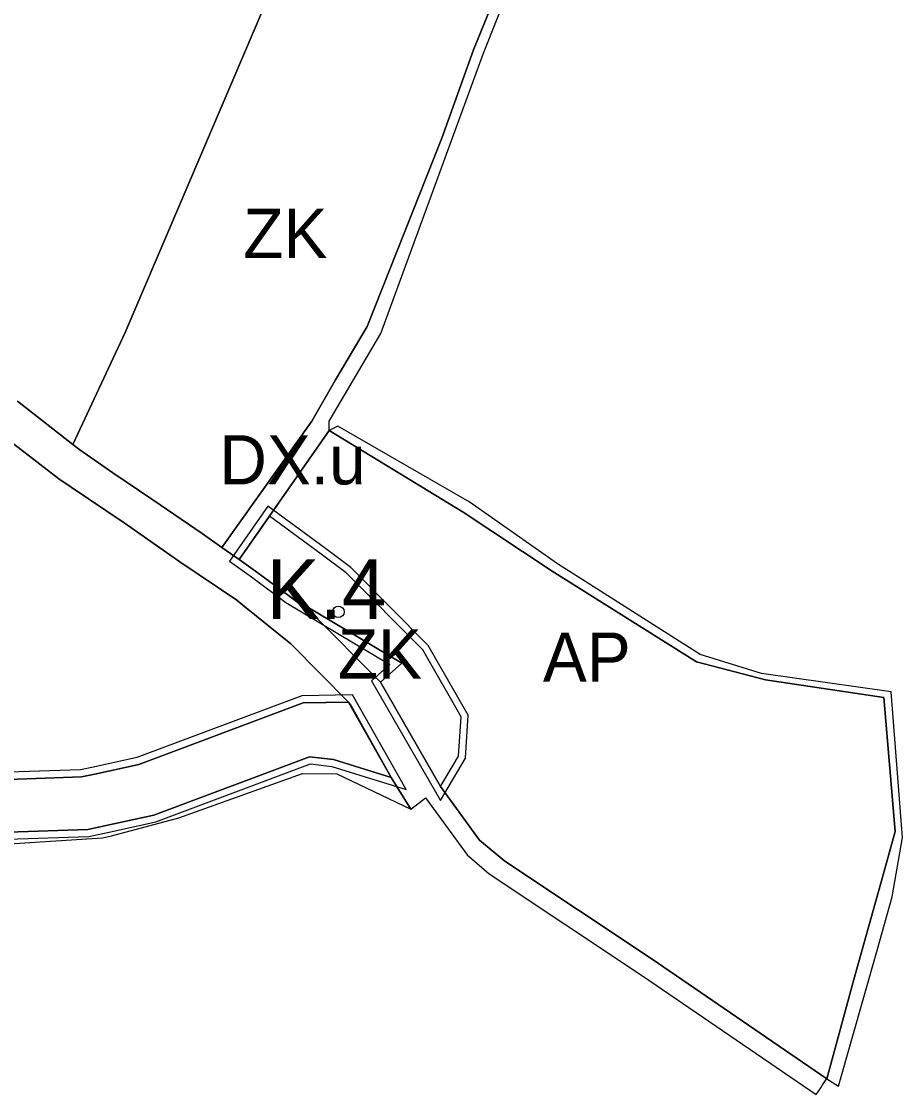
# Model space of a CAD drawing. Extents: x -555509 to -553005, y -1186756 to -1182560.
# Drawn here: x -553255.9 to -553005.3, y -1186113.4 to -1185808.2 of the extents above; entities that cross this region are included whole.
import ezdxf

# ---------------------------------------------------------------- set-up
doc = ezdxf.new("R2010")
doc.units = 0
for name, color, linetype in [('Level 26', 7, 'Continuous'), ('Level 46', 7, 'Continuous'), ('Level 56', 7, 'Continuous'), ('Level 59', 7, 'Continuous'), ('Level 63', 7, 'Continuous'), ('navrh_ZK', 7, 'Continuous'), ('OBRYS_PLOCH', 7, 'Continuous'), ('stav_AP', 7, 'Continuous'), ('stav_DS', 7, 'Continuous'), ('stav_ZK', 7, 'Continuous')]:
    doc.layers.add(name, color=color, linetype=linetype)

msp = doc.modelspace()

# ---------------------------------------------------------------- linework, layer by layer
at = {"layer": 'Level 26'}
for p, q in [((-553115.78, -1185787.77), (-553127.36, -1185816.34)), ((-553127.36, -1185816.34), (-553136.4, -1185841.45)), ((-553153.76, -1185896.92), (-553124.49, -1185817.28)), ((-553136.4, -1185841.45), (-553157.6, -1185894.95)), ((-553157.6, -1185894.95), (-553166.61, -1185910.14)), ((-553168.42, -1185921.93), (-553153.76, -1185896.92)), ((-553166.61, -1185910.14), (-553173.3, -1185921.88)), ((-553173.3, -1185921.88), (-553198.95, -1185957.78)), ((-553168.4, -1185924.59), (-553168.42, -1185921.93)), ((-553165.97, -1185923.29), (-553168.4, -1185924.59)), ((-553128.55, -1185944.85), (-553165.97, -1185923.29)), ((-553193.99, -1185961.2), (-553168.4, -1185924.59)), ((-553168.4, -1185924.59), (-553130.28, -1185947.73)), ((-553103.48, -1185962.47), (-553128.55, -1185944.85)), ((-553130.28, -1185947.73), (-553104.94, -1185964.54)), ((-553198.95, -1185957.78), (-553193.99, -1185961.2)), ((-553062.85, -1185988.25), (-553103.48, -1185962.47)), ((-553104.94, -1185964.54), (-553063.9, -1185990.3)), ((-553063.9, -1185990.3), (-553044.3, -1185995.42)), ((-553045.45, -1185993.67), (-553062.85, -1185988.25)), ((-553008.56, -1185998.82), (-553045.45, -1185993.67)), ((-553044.3, -1185995.42), (-553010.66, -1186000.44)), ((-553005.32, -1186040.24), (-553008.56, -1185998.82)), ((-553010.66, -1186000.44), (-553007.44, -1186038.58)), ((-553173.99, -1186017.29), (-553218.26, -1186033.91)), ((-553167.22, -1186018.11), (-553173.99, -1186017.29)), ((-553150.76, -1186023.24), (-553167.22, -1186018.11)), ((-553211.18, -1186034.68), (-553176, -1186022.03)), ((-553176, -1186022.03), (-553166.24, -1186022.15)), ((-553166.24, -1186022.15), (-553145.21, -1186032.25)), ((-553145.21, -1186032.25), (-553150.76, -1186023.24)), ((-553231.86, -1186036.89), (-553237.04, -1186038)), ((-553218.26, -1186033.91), (-553231.86, -1186036.89)), ((-553230.3, -1186039.79), (-553211.18, -1186034.68)), ((-553237.04, -1186038), (-553259.77, -1186038.75)), ((-553232.89, -1186040.35), (-553230.3, -1186039.79)), ((-553007.44, -1186038.58), (-553010.81, -1186050.92)), ((-553259.44, -1186042.1), (-553232.89, -1186040.35)), ((-553008.26, -1186057.11), (-553005.32, -1186040.24)), ((-553010.81, -1186050.92), (-553019.21, -1186080.66)), ((-553012.46, -1186071.98), (-553008.26, -1186057.11)), ((-553023.58, -1186111.01), (-553012.46, -1186071.98)), ((-553019.21, -1186080.66), (-553026.89, -1186108.94)), ((-553026.89, -1186108.94), (-553023.58, -1186111.01))]:
    msp.add_line(p, q, dxfattribs=at)
msp.add_lwpolyline([(-553124.49, -1185817.28), (-553113.19, -1185788.8), (-553092.08, -1185747)], dxfattribs=at)
at = {"layer": 'Level 46'}
msp.add_circle((-553165.8, -1185976.11), 1.64, dxfattribs=at)
at = {"layer": 'Level 56'}
msp.add_lwpolyline([(-553151.13, -1185991.04), (-553156.39, -1185995.71), (-553136.78, -1186029.78), (-553129.67, -1186017.76), (-553128.84, -1186005.49), (-553140.21, -1185985.72), (-553162.27, -1185963.5), (-553169.46, -1185958.13), (-553185.86, -1185946.08), (-553196.77, -1185961.68), (-553190.51, -1185966.12), (-553180.74, -1185973.41)], close=True, dxfattribs=at)
msp.add_lwpolyline([(-553259.79, -1186040.75), (-553236.8, -1186039.99), (-553231.44, -1186038.84), (-553217.69, -1186035.83), (-553173.74, -1186019.33), (-553167.64, -1186020.07), (-553146.53, -1186026.65), (-553161.75, -1185999.75), (-553176.21, -1185999.96), (-553223.09, -1186017.57), (-553235.46, -1186020.28), (-553239.12, -1186021.06), (-553259.56, -1186021.73)], dxfattribs=at)
at = {"layer": 'navrh_ZK'}
for p, q in [((-553193.99, -1185961.2), (-553189.33, -1185964.5)), ((-553189.33, -1185964.5), (-553179.63, -1185971.75)), ((-553179.63, -1185971.75), (-553147.76, -1185990.72)), ((-553147.76, -1185990.72), (-553153.84, -1185996.12)), ((-553153.84, -1185996.12), (-553136.76, -1186025.81))]:
    msp.add_line(p, q, dxfattribs=at)
for points in [[(-553136.76, -1186025.81), (-553131.64, -1186017.15), (-553130.88, -1186005.96), (-553141.82, -1185986.94), (-553163.58, -1185965.02), (-553170.65, -1185959.74), (-553185.4, -1185948.91), (-553193.99, -1185961.2)], [(-553259.77, -1186038.75), (-553237.04, -1186038), (-553231.86, -1186036.89), (-553218.26, -1186033.91), (-553173.99, -1186017.29), (-553167.22, -1186018.11), (-553150.76, -1186023.24), (-553162.91, -1186001.77), (-553175.83, -1186001.96), (-553222.52, -1186019.49), (-553235.04, -1186022.23), (-553238.87, -1186023.05), (-553259.58, -1186023.74)]]:
    msp.add_lwpolyline(points, dxfattribs=at)
at = {"layer": 'OBRYS_PLOCH'}
for p, q in [((-553127.36, -1185816.34), (-553115.78, -1185787.77)), ((-553115.78, -1185787.77), (-553127.36, -1185816.34)), ((-553186.75, -1185803.57), (-553220.66, -1185883.17)), ((-553220.66, -1185883.17), (-553186.75, -1185803.57)), ((-553136.4, -1185841.45), (-553127.36, -1185816.34)), ((-553127.36, -1185816.34), (-553136.4, -1185841.45)), ((-553153.76, -1185896.92), (-553124.49, -1185817.28)), ((-553157.6, -1185894.95), (-553136.4, -1185841.45)), ((-553136.4, -1185841.45), (-553157.6, -1185894.95)), ((-553220.66, -1185883.17), (-553226.41, -1185896.66)), ((-553226.41, -1185896.66), (-553220.66, -1185883.17)), ((-553166.61, -1185910.14), (-553157.6, -1185894.95)), ((-553157.6, -1185894.95), (-553166.61, -1185910.14)), ((-553226.41, -1185896.66), (-553241.32, -1185928.48)), ((-553241.32, -1185928.48), (-553226.41, -1185896.66)), ((-553168.42, -1185921.93), (-553153.76, -1185896.92)), ((-553173.3, -1185921.88), (-553166.61, -1185910.14)), ((-553166.61, -1185910.14), (-553173.3, -1185921.88)), ((-553257.04, -1185916.2), (-553241.32, -1185928.48)), ((-553241.32, -1185928.48), (-553257.04, -1185916.2)), ((-553266.45, -1185922.03), (-553254.85, -1185930.89)), ((-553254.85, -1185930.89), (-553266.45, -1185922.03)), ((-553254.85, -1185930.89), (-553266.45, -1185922.03)), ((-553198.95, -1185957.78), (-553173.3, -1185921.88)), ((-553173.3, -1185921.88), (-553198.95, -1185957.78)), ((-553168.4, -1185924.59), (-553168.42, -1185921.93)), ((-553165.97, -1185923.29), (-553168.4, -1185924.59)), ((-553128.55, -1185944.85), (-553165.97, -1185923.29)), ((-553193.99, -1185961.2), (-553168.4, -1185924.59)), ((-553168.4, -1185924.59), (-553193.99, -1185961.2)), ((-553168.4, -1185924.59), (-553130.28, -1185947.73)), ((-553130.28, -1185947.73), (-553168.4, -1185924.59)), ((-553241.32, -1185928.48), (-553239.31, -1185930.03)), ((-553239.31, -1185930.03), (-553241.32, -1185928.48)), ((-553239.31, -1185930.03), (-553229.98, -1185936.55)), ((-553229.98, -1185936.55), (-553239.31, -1185930.03)), ((-553254.85, -1185930.89), (-553245.34, -1185938.26)), ((-553245.34, -1185938.26), (-553254.85, -1185930.89)), ((-553245.34, -1185938.26), (-553254.85, -1185930.89)), ((-553245.34, -1185938.26), (-553241.85, -1185940.7)), ((-553241.85, -1185940.7), (-553245.34, -1185938.26)), ((-553241.85, -1185940.7), (-553245.34, -1185938.26)), ((-553229.98, -1185936.55), (-553218.58, -1185944.24)), ((-553218.58, -1185944.24), (-553229.98, -1185936.55)), ((-553241.85, -1185940.7), (-553226.71, -1185950.81)), ((-553226.71, -1185950.81), (-553241.85, -1185940.7)), ((-553226.71, -1185950.81), (-553241.85, -1185940.7)), ((-553218.58, -1185944.24), (-553204.56, -1185953.8)), ((-553204.56, -1185953.8), (-553218.58, -1185944.24)), ((-553103.48, -1185962.47), (-553128.55, -1185944.85)), ((-553130.28, -1185947.73), (-553104.94, -1185964.54)), ((-553104.94, -1185964.54), (-553130.28, -1185947.73)), ((-553226.71, -1185950.81), (-553210.92, -1185961.87)), ((-553210.92, -1185961.87), (-553226.71, -1185950.81)), ((-553210.92, -1185961.87), (-553226.71, -1185950.81)), ((-553204.56, -1185953.8), (-553198.95, -1185957.78)), ((-553198.95, -1185957.78), (-553204.56, -1185953.8)), ((-553198.95, -1185957.78), (-553193.99, -1185961.2)), ((-553193.99, -1185961.2), (-553198.95, -1185957.78)), ((-553210.92, -1185961.87), (-553194.72, -1185972.77)), ((-553194.72, -1185972.77), (-553210.92, -1185961.87)), ((-553194.72, -1185972.77), (-553210.92, -1185961.87)), ((-553193.99, -1185961.2), (-553189.33, -1185964.5)), ((-553193.99, -1185961.2), (-553189.33, -1185964.5)), ((-553189.33, -1185964.5), (-553193.99, -1185961.2)), ((-553062.85, -1185988.25), (-553103.48, -1185962.47)), ((-553189.33, -1185964.5), (-553179.63, -1185971.75)), ((-553189.33, -1185964.5), (-553179.63, -1185971.75)), ((-553179.63, -1185971.75), (-553189.33, -1185964.5)), ((-553104.94, -1185964.54), (-553063.9, -1185990.3)), ((-553063.9, -1185990.3), (-553104.94, -1185964.54)), ((-553194.72, -1185972.77), (-553192.48, -1185974.58)), ((-553192.48, -1185974.58), (-553194.72, -1185972.77)), ((-553192.48, -1185974.58), (-553194.72, -1185972.77)), ((-553147.76, -1185990.72), (-553179.63, -1185971.75)), ((-553179.63, -1185971.75), (-553173.45, -1185976.37)), ((-553179.63, -1185971.75), (-553147.76, -1185990.72)), ((-553179.63, -1185971.75), (-553147.76, -1185990.72)), ((-553173.45, -1185976.37), (-553179.63, -1185971.75)), ((-553192.48, -1185974.58), (-553179.3, -1185985.16)), ((-553179.3, -1185985.16), (-553192.48, -1185974.58)), ((-553179.3, -1185985.16), (-553192.48, -1185974.58)), ((-553173.45, -1185976.37), (-553153.84, -1185996.12)), ((-553153.84, -1185996.12), (-553173.45, -1185976.37)), ((-553179.3, -1185985.16), (-553162.91, -1186001.77)), ((-553162.91, -1186001.77), (-553179.3, -1185985.16)), ((-553162.91, -1186001.77), (-553179.3, -1185985.16)), ((-553153.84, -1185996.12), (-553147.76, -1185990.72)), ((-553147.76, -1185990.72), (-553153.84, -1185996.12)), ((-553147.76, -1185990.72), (-553153.84, -1185996.12)), ((-553063.9, -1185990.3), (-553044.3, -1185995.42)), ((-553044.3, -1185995.42), (-553063.9, -1185990.3)), ((-553045.45, -1185993.67), (-553062.85, -1185988.25)), ((-553008.56, -1185998.82), (-553045.45, -1185993.67)), ((-553153.84, -1185996.12), (-553136.76, -1186025.81)), ((-553153.84, -1185996.12), (-553136.76, -1186025.81)), ((-553136.76, -1186025.81), (-553153.84, -1185996.12)), ((-553044.3, -1185995.42), (-553010.66, -1186000.44)), ((-553010.66, -1186000.44), (-553044.3, -1185995.42)), ((-553005.32, -1186040.24), (-553008.56, -1185998.82)), ((-553175.83, -1186001.96), (-553162.91, -1186001.77)), ((-553162.91, -1186001.77), (-553162.15, -1186002.81)), ((-553162.15, -1186002.81), (-553150.76, -1186023.24)), ((-553010.66, -1186000.44), (-553007.44, -1186038.58)), ((-553007.44, -1186038.58), (-553010.66, -1186000.44)), ((-553173.99, -1186017.29), (-553218.26, -1186033.91)), ((-553167.22, -1186018.11), (-553173.99, -1186017.29)), ((-553150.76, -1186023.24), (-553167.22, -1186018.11)), ((-553259.58, -1186023.74), (-553238.87, -1186023.05)), ((-553238.87, -1186023.05), (-553235.04, -1186022.23)), ((-553211.18, -1186034.68), (-553176, -1186022.03)), ((-553176, -1186022.03), (-553166.24, -1186022.15)), ((-553166.24, -1186022.15), (-553145.21, -1186032.25)), ((-553145.21, -1186032.25), (-553150.76, -1186023.24)), ((-553150.76, -1186023.24), (-553145.21, -1186032.25)), ((-553136.76, -1186025.81), (-553125.63, -1186041.03)), ((-553125.63, -1186041.03), (-553136.76, -1186025.81)), ((-553144.08, -1186031.39), (-553140.98, -1186029.03)), ((-553140.98, -1186029.03), (-553134.27, -1186038.23)), ((-553145.21, -1186032.25), (-553144.32, -1186031.58)), ((-553144.32, -1186031.58), (-553144.08, -1186031.39)), ((-553231.86, -1186036.89), (-553237.04, -1186038)), ((-553218.26, -1186033.91), (-553231.86, -1186036.89)), ((-553230.3, -1186039.79), (-553211.18, -1186034.68)), ((-553237.04, -1186038), (-553259.77, -1186038.75)), ((-553232.89, -1186040.35), (-553230.3, -1186039.79)), ((-553134.27, -1186038.23), (-553129.21, -1186045.17)), ((-553007.44, -1186038.58), (-553010.81, -1186050.92)), ((-553010.81, -1186050.92), (-553007.44, -1186038.58)), ((-553259.44, -1186042.1), (-553232.89, -1186040.35)), ((-553125.63, -1186041.03), (-553118.41, -1186046.97)), ((-553118.41, -1186046.97), (-553125.63, -1186041.03)), ((-553008.26, -1186057.11), (-553005.32, -1186040.24)), ((-553129.21, -1186045.17), (-553122.89, -1186050.56)), ((-553118.41, -1186046.97), (-553076.51, -1186074.88)), ((-553076.51, -1186074.88), (-553118.41, -1186046.97)), ((-553122.89, -1186050.56), (-553079.26, -1186079.6)), ((-553010.81, -1186050.92), (-553019.21, -1186080.66)), ((-553019.21, -1186080.66), (-553010.81, -1186050.92)), ((-553012.46, -1186071.98), (-553008.26, -1186057.11)), ((-553023.58, -1186111.01), (-553012.46, -1186071.98)), ((-553076.51, -1186074.88), (-553026.89, -1186108.94)), ((-553026.89, -1186108.94), (-553076.51, -1186074.88)), ((-553019.21, -1186080.66), (-553026.89, -1186108.94)), ((-553026.89, -1186108.94), (-553019.21, -1186080.66)), ((-553026.89, -1186108.94), (-553023.58, -1186111.01))]:
    msp.add_line(p, q, dxfattribs=at)
for points in [[(-553124.49, -1185817.28), (-553113.19, -1185788.8), (-553092.08, -1185747)], [(-553136.76, -1186025.81), (-553131.64, -1186017.15), (-553130.88, -1186005.96), (-553141.82, -1185986.94), (-553163.58, -1185965.02), (-553170.65, -1185959.74), (-553185.4, -1185948.91), (-553193.99, -1185961.2)], [(-553259.77, -1186038.75), (-553237.04, -1186038), (-553231.86, -1186036.89), (-553218.26, -1186033.91), (-553173.99, -1186017.29), (-553167.22, -1186018.11), (-553150.76, -1186023.24), (-553162.91, -1186001.77), (-553175.83, -1186001.96), (-553222.52, -1186019.49), (-553235.04, -1186022.23), (-553238.87, -1186023.05), (-553259.58, -1186023.74)], [(-553235.04, -1186022.23), (-553222.52, -1186019.49), (-553175.83, -1186001.96)], [(-553222.52, -1186019.49), (-553175.83, -1186001.96), (-553162.91, -1186001.77)], [(-553307.71, -1186025.17), (-553282.02, -1186022.43), (-553259.58, -1186023.74), (-553238.87, -1186023.05), (-553235.04, -1186022.23), (-553222.52, -1186019.49)], [(-553079.26, -1186079.6), (-553029.85, -1186113.36), (-553028.59, -1186111.48), (-553028.14, -1186110.81), (-553027.02, -1186109.13), (-553026.89, -1186108.94)]]:
    msp.add_lwpolyline(points, dxfattribs=at)
at = {"layer": 'stav_AP'}
for p, q in [((-553220.66, -1185883.17), (-553186.75, -1185803.57)), ((-553226.41, -1185896.66), (-553220.66, -1185883.17)), ((-553241.32, -1185928.48), (-553226.41, -1185896.66)), ((-553257.04, -1185916.2), (-553241.32, -1185928.48)), ((-553254.85, -1185930.89), (-553266.45, -1185922.03)), ((-553168.4, -1185924.59), (-553193.99, -1185961.2)), ((-553130.28, -1185947.73), (-553168.4, -1185924.59)), ((-553245.34, -1185938.26), (-553254.85, -1185930.89)), ((-553241.85, -1185940.7), (-553245.34, -1185938.26)), ((-553226.71, -1185950.81), (-553241.85, -1185940.7)), ((-553104.94, -1185964.54), (-553130.28, -1185947.73)), ((-553210.92, -1185961.87), (-553226.71, -1185950.81)), ((-553194.72, -1185972.77), (-553210.92, -1185961.87)), ((-553193.99, -1185961.2), (-553189.33, -1185964.5)), ((-553189.33, -1185964.5), (-553179.63, -1185971.75)), ((-553063.9, -1185990.3), (-553104.94, -1185964.54)), ((-553192.48, -1185974.58), (-553194.72, -1185972.77)), ((-553179.63, -1185971.75), (-553147.76, -1185990.72)), ((-553179.3, -1185985.16), (-553192.48, -1185974.58)), ((-553162.91, -1186001.77), (-553179.3, -1185985.16)), ((-553147.76, -1185990.72), (-553153.84, -1185996.12)), ((-553044.3, -1185995.42), (-553063.9, -1185990.3)), ((-553153.84, -1185996.12), (-553136.76, -1186025.81)), ((-553010.66, -1186000.44), (-553044.3, -1185995.42)), ((-553222.52, -1186019.49), (-553175.83, -1186001.96)), ((-553175.83, -1186001.96), (-553162.91, -1186001.77)), ((-553007.44, -1186038.58), (-553010.66, -1186000.44)), ((-553235.04, -1186022.23), (-553222.52, -1186019.49)), ((-553259.58, -1186023.74), (-553238.87, -1186023.05)), ((-553238.87, -1186023.05), (-553235.04, -1186022.23)), ((-553136.76, -1186025.81), (-553125.63, -1186041.03)), ((-553010.81, -1186050.92), (-553007.44, -1186038.58)), ((-553125.63, -1186041.03), (-553118.41, -1186046.97)), ((-553118.41, -1186046.97), (-553076.51, -1186074.88)), ((-553019.21, -1186080.66), (-553010.81, -1186050.92)), ((-553076.51, -1186074.88), (-553026.89, -1186108.94)), ((-553026.89, -1186108.94), (-553019.21, -1186080.66))]:
    msp.add_line(p, q, dxfattribs=at)
at = {"layer": 'stav_DS'}
for p, q in [((-553241.32, -1185928.48), (-553257.04, -1185916.2)), ((-553266.45, -1185922.03), (-553254.85, -1185930.89)), ((-553239.31, -1185930.03), (-553241.32, -1185928.48)), ((-553229.98, -1185936.55), (-553239.31, -1185930.03)), ((-553254.85, -1185930.89), (-553245.34, -1185938.26)), ((-553245.34, -1185938.26), (-553241.85, -1185940.7)), ((-553218.58, -1185944.24), (-553229.98, -1185936.55)), ((-553241.85, -1185940.7), (-553226.71, -1185950.81)), ((-553204.56, -1185953.8), (-553218.58, -1185944.24)), ((-553226.71, -1185950.81), (-553210.92, -1185961.87)), ((-553198.95, -1185957.78), (-553204.56, -1185953.8)), ((-553193.99, -1185961.2), (-553198.95, -1185957.78)), ((-553210.92, -1185961.87), (-553194.72, -1185972.77)), ((-553189.33, -1185964.5), (-553193.99, -1185961.2)), ((-553179.63, -1185971.75), (-553189.33, -1185964.5)), ((-553194.72, -1185972.77), (-553192.48, -1185974.58)), ((-553173.45, -1185976.37), (-553179.63, -1185971.75)), ((-553192.48, -1185974.58), (-553179.3, -1185985.16)), ((-553153.84, -1185996.12), (-553173.45, -1185976.37)), ((-553179.3, -1185985.16), (-553162.91, -1186001.77)), ((-553136.76, -1186025.81), (-553153.84, -1185996.12)), ((-553162.91, -1186001.77), (-553162.15, -1186002.81)), ((-553162.15, -1186002.81), (-553150.76, -1186023.24)), ((-553150.76, -1186023.24), (-553145.21, -1186032.25)), ((-553125.63, -1186041.03), (-553136.76, -1186025.81)), ((-553144.08, -1186031.39), (-553140.98, -1186029.03)), ((-553140.98, -1186029.03), (-553134.27, -1186038.23)), ((-553145.21, -1186032.25), (-553144.32, -1186031.58)), ((-553144.32, -1186031.58), (-553144.08, -1186031.39)), ((-553134.27, -1186038.23), (-553129.21, -1186045.17)), ((-553118.41, -1186046.97), (-553125.63, -1186041.03)), ((-553129.21, -1186045.17), (-553122.89, -1186050.56)), ((-553076.51, -1186074.88), (-553118.41, -1186046.97)), ((-553122.89, -1186050.56), (-553079.26, -1186079.6)), ((-553026.89, -1186108.94), (-553076.51, -1186074.88))]:
    msp.add_line(p, q, dxfattribs=at)
msp.add_lwpolyline([(-553079.26, -1186079.6), (-553029.85, -1186113.36), (-553028.59, -1186111.48), (-553028.14, -1186110.81), (-553027.02, -1186109.13), (-553026.89, -1186108.94)], dxfattribs=at)
at = {"layer": 'stav_ZK'}
for p, q in [((-553127.36, -1185816.34), (-553115.78, -1185787.77)), ((-553186.75, -1185803.57), (-553220.66, -1185883.17)), ((-553136.4, -1185841.45), (-553127.36, -1185816.34)), ((-553157.6, -1185894.95), (-553136.4, -1185841.45)), ((-553220.66, -1185883.17), (-553226.41, -1185896.66)), ((-553166.61, -1185910.14), (-553157.6, -1185894.95)), ((-553226.41, -1185896.66), (-553241.32, -1185928.48)), ((-553173.3, -1185921.88), (-553166.61, -1185910.14)), ((-553198.95, -1185957.78), (-553173.3, -1185921.88)), ((-553241.32, -1185928.48), (-553239.31, -1185930.03)), ((-553239.31, -1185930.03), (-553229.98, -1185936.55)), ((-553229.98, -1185936.55), (-553218.58, -1185944.24)), ((-553218.58, -1185944.24), (-553204.56, -1185953.8)), ((-553204.56, -1185953.8), (-553198.95, -1185957.78)), ((-553147.76, -1185990.72), (-553179.63, -1185971.75)), ((-553179.63, -1185971.75), (-553173.45, -1185976.37)), ((-553173.45, -1185976.37), (-553153.84, -1185996.12)), ((-553153.84, -1185996.12), (-553147.76, -1185990.72))]:
    msp.add_line(p, q, dxfattribs=at)

# ---------------------------------------------------------------- texts
at = {"layer": 'Level 46'}
msp.add_text('K.4', height=17, dxfattribs=at).set_placement((-553186.26, -1185978.13))
at = {"layer": 'Level 59'}
for s, p in [('ZK', (-553192.83, -1185875.49)), ('DX.u', (-553199.65, -1185939.87)), ('AP', (-553107.62, -1185995.99))]:
    msp.add_text(s, height=14, dxfattribs=at).set_placement(p)
at = {"layer": 'Level 63'}
msp.add_text('ZK', height=14, dxfattribs=at).set_placement((-553165.97, -1185995.07))

doc.saveas('drawing.dxf')
